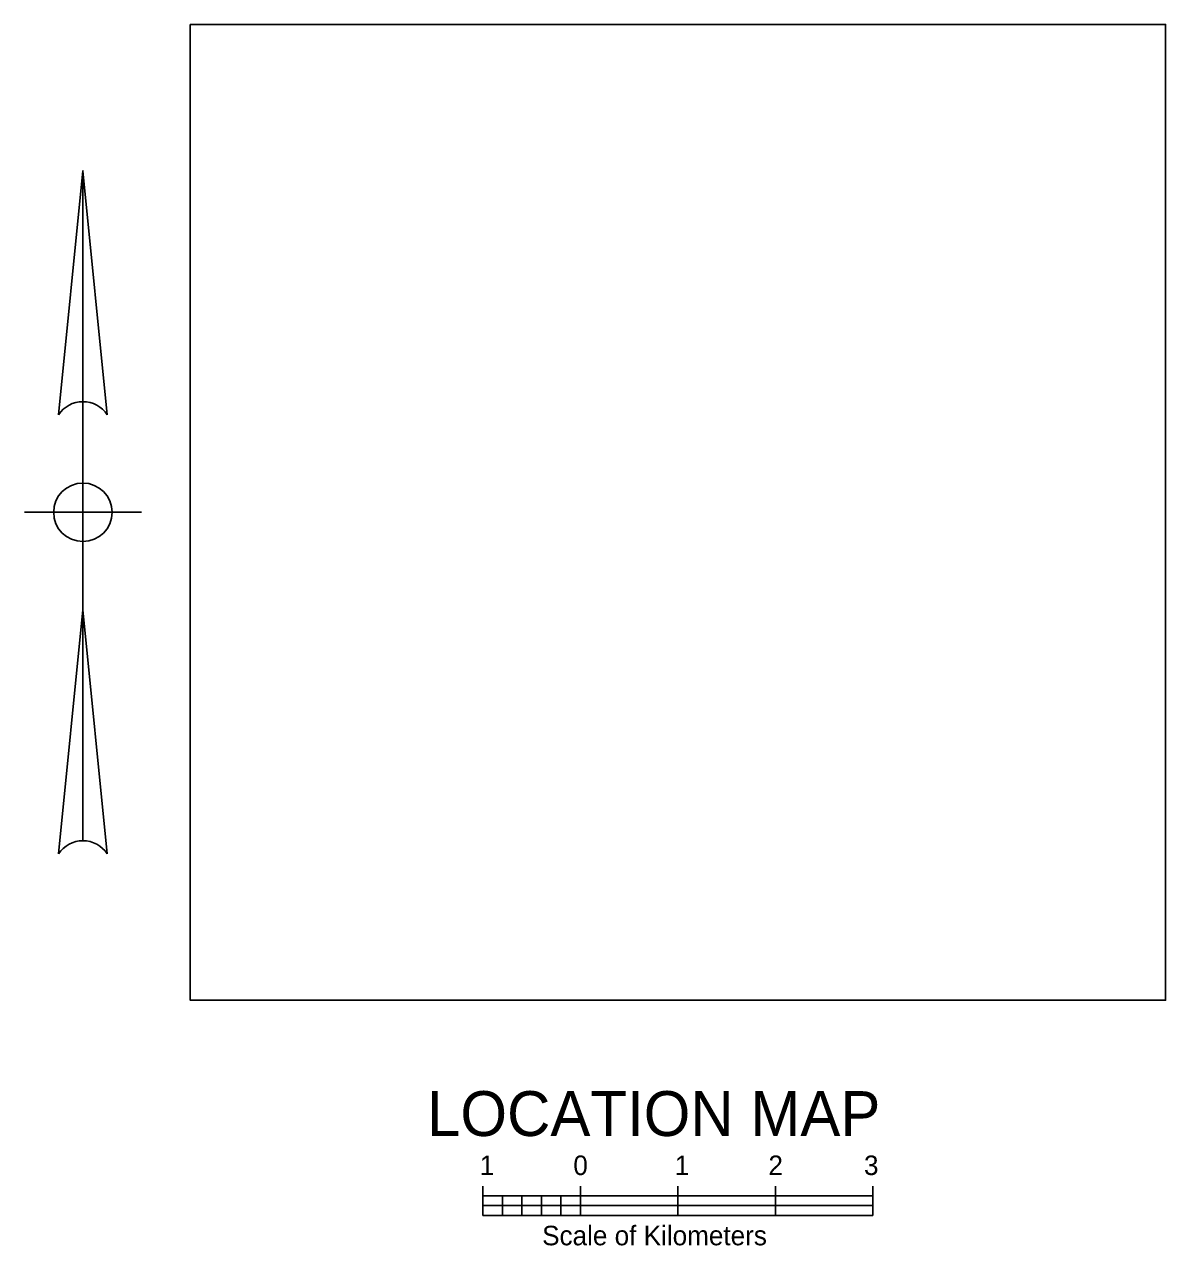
# Model space of a CAD drawing. Extents: x 605371.3 to 605398.1, y 420183.2 to 420214.1.
# Drawn here: x 605390.3683 to 605390.4853, y 420198.9816 to 420199.1067 of the extents above; entities that cross this region are included whole.
import ezdxf

# ---------------------------------------------------------------- set-up
doc = ezdxf.new("R2010")
doc.units = 0
doc.layers.add('Level 1', color=7, linetype='Continuous')
doc.layers.add('Notes', color=7, linetype='Continuous')

msp = doc.modelspace()

# ---------------------------------------------------------------- linework, layer by layer
at = {"layer": 'Level 1'}
for p, q in [((605390.37432, 420199.09172), (605390.37432, 420199.02306)), ((605390.37432, 420199.09172), (605390.37432, 420199.02306)), ((605390.36832, 420199.05672), (605390.38032, 420199.05672)), ((605390.36832, 420199.05672), (605390.38032, 420199.05672))]:
    msp.add_line(p, q, dxfattribs=at)
for points in [[(605390.37182, 420199.06672), (605390.37432, 420199.09172), (605390.37682, 420199.06672)], [(605390.37182, 420199.06672), (605390.37432, 420199.09172), (605390.37682, 420199.06672)], [(605390.37182, 420199.02172), (605390.37432, 420199.04672), (605390.37682, 420199.02172)], [(605390.37182, 420199.02172), (605390.37432, 420199.04672), (605390.37682, 420199.02172)]]:
    msp.add_lwpolyline(points, dxfattribs=at)
msp.add_circle((605390.37432, 420199.05672), 0.003, dxfattribs=at)
msp.add_circle((605390.37432, 420199.05672), 0.003, dxfattribs=at)
for centre in [(605390.37432, 420199.06506), (605390.37432, 420199.06506), (605390.37432, 420199.02006), (605390.37432, 420199.02006)]:
    msp.add_arc(centre, 0.003, 33.5573, 146.4427, dxfattribs=at)
at = {"layer": 'Notes'}
for p, q in [((605390.41532, 420198.98767), (605390.41532, 420198.98467)), ((605390.41532, 420198.98767), (605390.41532, 420198.98467)), ((605390.42532, 420198.98767), (605390.42532, 420198.98467)), ((605390.42532, 420198.98767), (605390.42532, 420198.98467)), ((605390.43532, 420198.98767), (605390.43532, 420198.98467)), ((605390.43532, 420198.98767), (605390.43532, 420198.98467)), ((605390.44532, 420198.98767), (605390.44532, 420198.98467)), ((605390.44532, 420198.98767), (605390.44532, 420198.98467)), ((605390.45532, 420198.98767), (605390.45532, 420198.98467)), ((605390.45532, 420198.98767), (605390.45532, 420198.98467)), ((605390.41532, 420198.98667), (605390.45532, 420198.98667)), ((605390.41532, 420198.98667), (605390.45532, 420198.98667)), ((605390.41732, 420198.98667), (605390.41732, 420198.98467)), ((605390.41732, 420198.98667), (605390.41732, 420198.98467)), ((605390.41932, 420198.98667), (605390.41932, 420198.98467)), ((605390.41932, 420198.98667), (605390.41932, 420198.98467)), ((605390.42132, 420198.98667), (605390.42132, 420198.98467)), ((605390.42132, 420198.98667), (605390.42132, 420198.98467)), ((605390.42332, 420198.98667), (605390.42332, 420198.98467)), ((605390.42332, 420198.98667), (605390.42332, 420198.98467)), ((605390.41532, 420198.98567), (605390.45532, 420198.98567)), ((605390.41532, 420198.98567), (605390.45532, 420198.98567)), ((605390.41532, 420198.98467), (605390.45532, 420198.98467)), ((605390.41532, 420198.98467), (605390.45532, 420198.98467))]:
    msp.add_line(p, q, dxfattribs=at)
msp.add_lwpolyline([(605390.38532, 420199.10672), (605390.48532, 420199.10672), (605390.48532, 420199.00672), (605390.38532, 420199.00672)], close=True, dxfattribs=at)
msp.add_lwpolyline([(605390.38532, 420199.10672), (605390.48532, 420199.10672), (605390.48532, 420199.00672), (605390.38532, 420199.00672)], close=True, dxfattribs=at)

# ---------------------------------------------------------------- texts
for s, height, p in [('LOCATION MAP', 0.0045996, (605390.4096, 420198.9928)), ('LOCATION MAP', 0.0045996, (605390.4096, 420198.9928)), ('1', 0.002, (605390.415, 420198.9888)), ('1', 0.002, (605390.415, 420198.9888)), ('0', 0.002, (605390.4246, 420198.9888)), ('0', 0.002, (605390.4246, 420198.9888)), ('1', 0.002, (605390.435, 420198.9888)), ('1', 0.002, (605390.435, 420198.9888)), ('2', 0.002, (605390.4446, 420198.9888)), ('2', 0.002, (605390.4446, 420198.9888)), ('3', 0.002, (605390.4544, 420198.9888)), ('3', 0.002, (605390.4544, 420198.9888)), ('Scale of Kilometers', 0.0020004, (605390.4214, 420198.9816)), ('Scale of Kilometers', 0.0020004, (605390.4214, 420198.9816))]:
    msp.add_text(s, height=height, dxfattribs=at).set_placement(p)

doc.saveas('drawing.dxf')
